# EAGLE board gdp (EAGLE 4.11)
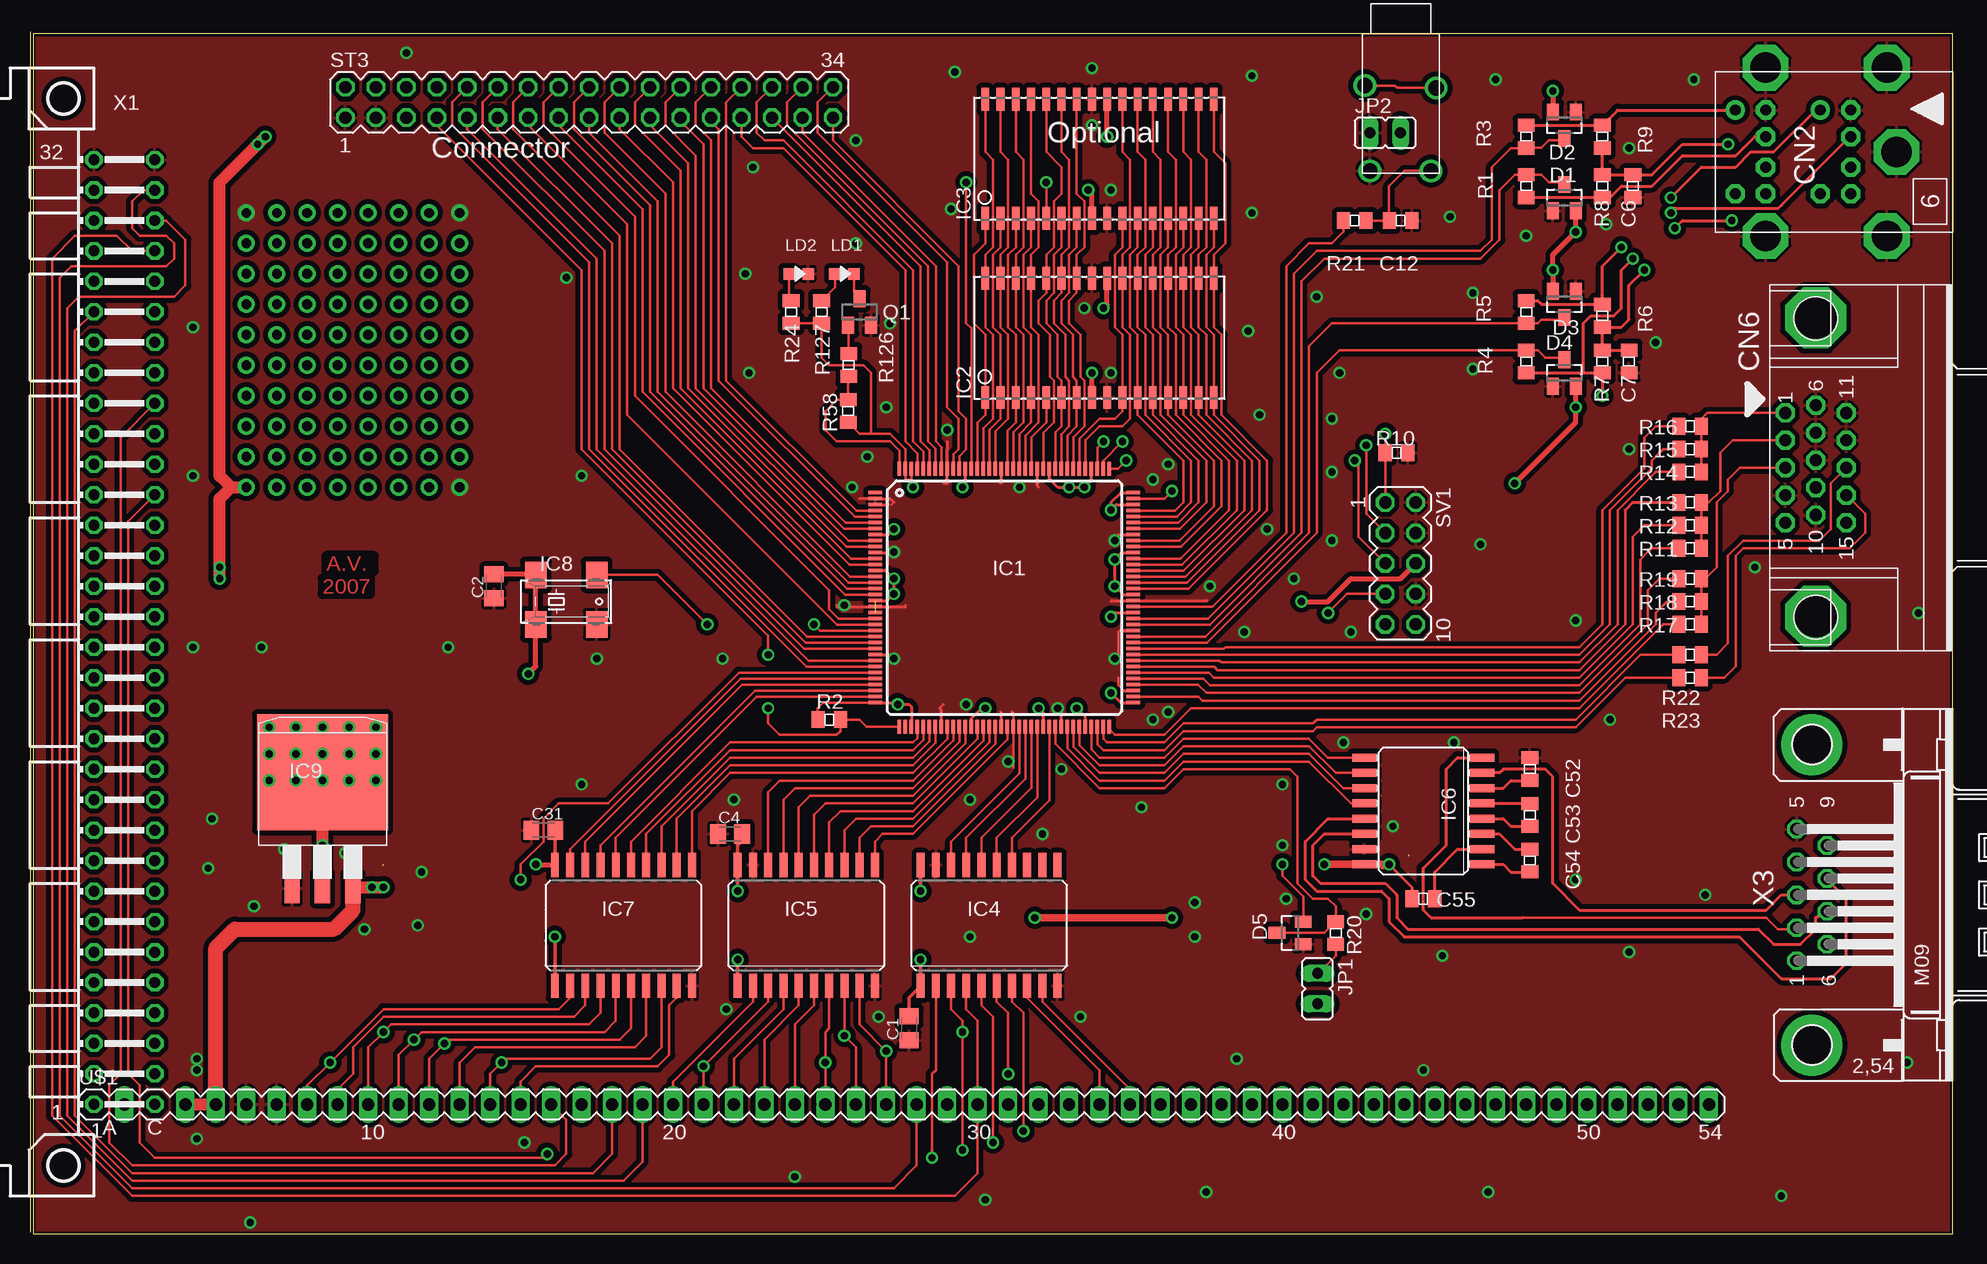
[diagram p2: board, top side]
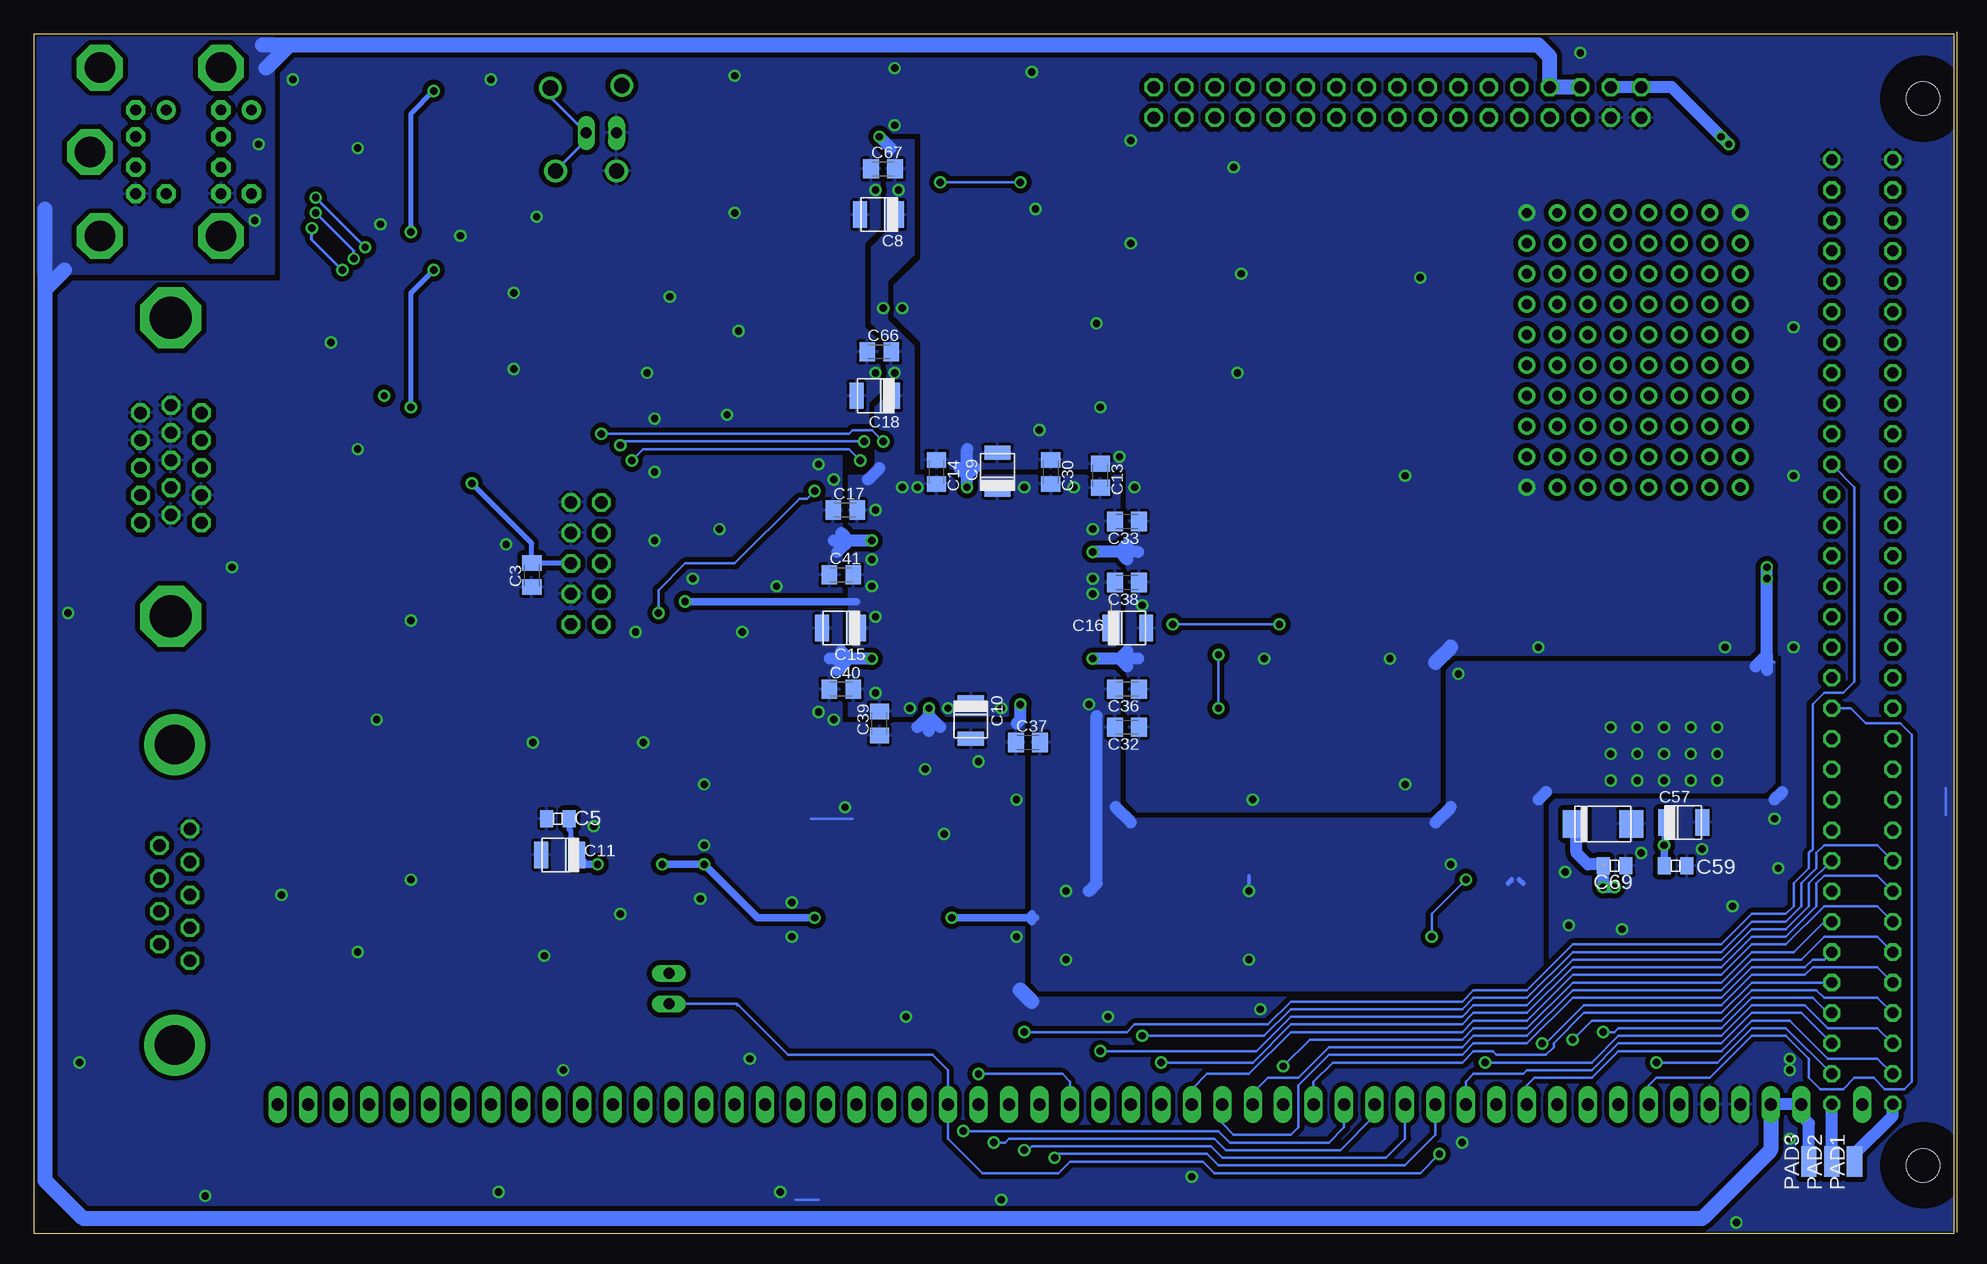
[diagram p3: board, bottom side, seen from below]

Size 160.25 x 100.18 mm. Coordinates in mm from the lower left corner, seen from the top.
Outline: 0.25,0 160.25,0 160.25,100 0.25,100 0.25,0
Copper layers (1*16): Top 0.035mm / dielectric 1.5mm / Bottom 0.035mm
Design rules "default": minimum track width 8mil, minimum drill 24mil, track to track 8mil, track to pad 8mil, pad to pad 8mil, via to via 8mil, smd to smd 8mil, copper to edge 0mil, drill to drill 8mil, minimum pad ring 10mil, minimum via ring 8mil, stop-mask expansion 4mil, vias tented up to drill 30mil, thermal gap 10mil

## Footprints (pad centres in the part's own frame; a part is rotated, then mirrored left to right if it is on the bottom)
C0805K = smd 1.3 x 1.6: 1 -1,0; 2 1,0
0805 = smd 1.092 x 1.397: 1 -0.94,0; 2 0.94,0
TANT_B = smd 1.15 x 2.2: 1 -1.473,0; 2 1.6,0
TANT_C = smd 2 x 2.3: 1 -2.032,0; 2 2.667,0
KLINKE3,5 = drill 1.27 round: 1 4.31,0.2; 2 11.43,0.635; 3 11.43,5.715; 4 4.51,6.15
MINIDIN_6POL_DOUBLE = drill 0.914 pad 1.6 octagon: A1 1.27,-8.5; A2 -1.27,-8.5; A3 3.493,-8.5; A4 -3.493,-8.5; A5 3.493,-11.04; B1 1.27,-15.6; B2 -1.27,-15.6; B3 3.493,-15.6; B4 -3.493,-15.6; B5 3.493,-18.14 | drill 0.914 pad 1.6 round: A6 -3.493,-11.04; B6 -3.493,-18.14 | drill 2.54 pad 3.81 octagon: SH1 0,-4.69; SH2 -7.018,-5.5; SH3 7.018,-5.5; SH4 -7.018,-15.6; SH5 7.018,-15.6
D-HD15F2 = drill 1.016 pad 1.575 octagon: 1 -4.826,-2.54; 2 -2.54,-2.54; 3 -0.254,-2.54; 4 2.032,-2.54; 5 4.318,-2.54; 6 -5.461,0; 7 -3.175,0; 8 -0.889,0; 9 1.397,0; 10 3.683,0; 11 -4.826,2.54; 12 -2.54,2.54; 13 -0.254,2.54; 14 2.032,2.54; 15 4.318,2.54 | drill 3.5 pad 5.08 octagon: PAD1 -12.754,0; PAD2 12.138,0
SOT23 = smd 1 x 1.4: 1 -0.95,-1.1; 2 0.95,-1.1; 3 0,1.1
TQFP144 = smd 1.143 x 0.297: 1 -10.75,8.75; 2 -10.75,8.25; 3 -10.75,7.75; 4 -10.75,7.25; 5 -10.75,6.75; 6 -10.75,6.25; 7 -10.75,5.75; 8 -10.75,5.25; 9 -10.75,4.75; 10 -10.75,4.25; 11 -10.75,3.75; 12 -10.75,3.25; 13 -10.75,2.75; 14 -10.75,2.25; 15 -10.75,1.75; 16 -10.75,1.25; 17 -10.75,0.75; 18 -10.75,0.25; 19 -10.75,-0.25; 20 -10.75,-0.75; 21 -10.75,-1.25; 22 -10.75,-1.75; 23 -10.75,-2.25; 24 -10.75,-2.75; 25 -10.75,-3.25; 26 -10.75,-3.75; 27 -10.75,-4.25; 28 -10.75,-4.75; 29 -10.75,-5.25; 30 -10.75,-5.75; 31 -10.75,-6.25; 32 -10.75,-6.75; 33 -10.75,-7.25; 34 -10.75,-7.75; 35 -10.75,-8.25; 36 -10.75,-8.75; 73 10.75,-8.75; 74 10.75,-8.25; 75 10.75,-7.75; 76 10.75,-7.25; 77 10.75,-6.75; 78 10.75,-6.25; 79 10.75,-5.75; 80 10.75,-5.25; 81 10.75,-4.75; 82 10.75,-4.25; 83 10.75,-3.75; 84 10.75,-3.25; 85 10.75,-2.75; 86 10.75,-2.25; 87 10.75,-1.75; 88 10.75,-1.25; 89 10.75,-0.75; 90 10.75,-0.25; 91 10.75,0.25; 92 10.75,0.75; 93 10.75,1.25; 94 10.75,1.75; 95 10.75,2.25; 96 10.75,2.75; 97 10.75,3.25; 98 10.75,3.75; 99 10.75,4.25; 100 10.75,4.75; 101 10.75,5.25; 102 10.75,5.75; 103 10.75,6.25; 104 10.75,6.75; 105 10.75,7.25; 106 10.75,7.75; 107 10.75,8.25; 108 10.75,8.75 | smd 0.297 x 1.143: 37 -8.75,-10.75; 38 -8.25,-10.75; 39 -7.75,-10.75; 40 -7.25,-10.75; 41 -6.75,-10.75; 42 -6.25,-10.75; 43 -5.75,-10.75; 44 -5.25,-10.75; 45 -4.75,-10.75; 46 -4.25,-10.75; 47 -3.75,-10.75; 48 -3.25,-10.75; 49 -2.75,-10.75; 50 -2.25,-10.75; 51 -1.75,-10.75; 52 -1.25,-10.75; 53 -0.75,-10.75; 54 -0.25,-10.75; 55 0.25,-10.75; 56 0.75,-10.75; 57 1.25,-10.75; 58 1.75,-10.75; 59 2.25,-10.75; 60 2.75,-10.75; 61 3.25,-10.75; 62 3.75,-10.75; 63 4.25,-10.75; 64 4.75,-10.75; 65 5.25,-10.75; 66 5.75,-10.75; 67 6.25,-10.75; 68 6.75,-10.75; 69 7.25,-10.75; 70 7.75,-10.75; 71 8.25,-10.75; 72 8.75,-10.75; 109 8.75,10.75; 110 8.25,10.75; 111 7.75,10.75; 112 7.25,10.75; 113 6.75,10.75; 114 6.25,10.75; 115 5.75,10.75; 116 5.25,10.75; 117 4.75,10.75; 118 4.25,10.75; 119 3.75,10.75; 120 3.25,10.75; 121 2.75,10.75; 122 2.25,10.75; 123 1.75,10.75; 124 1.25,10.75; 125 0.75,10.75; 126 0.25,10.75; 127 -0.25,10.75; 128 -0.75,10.75; 129 -1.25,10.75; 130 -1.75,10.75; 131 -2.25,10.75; 132 -2.75,10.75; 133 -3.25,10.75; 134 -3.75,10.75; 135 -4.25,10.75; 136 -4.75,10.75; 137 -5.25,10.75; 138 -5.75,10.75; 139 -6.25,10.75; 140 -6.75,10.75; 141 -7.25,10.75; 142 -7.75,10.75; 143 -8.25,10.75; 144 -8.75,10.75
SOJ32/4 = smd 0.635 x 1.905: 1 -8.89,-4.902; 2 -7.62,-4.902; 3 -6.35,-4.902; 4 -5.08,-4.902; 5 -3.81,-4.902; 6 -2.54,-4.902; 7 -1.27,-4.902; 8 0,-4.902; 9 1.27,-4.902; 10 2.54,-4.902; 11 3.81,-4.902; 12 5.08,-4.902; 13 6.35,-4.902; 14 7.62,-4.902; 15 8.89,-4.902; 16 10.16,-4.902; 17 10.16,5.029; 18 8.89,5.029; 19 7.62,5.029; 20 6.35,5.029; 21 5.08,5.029; 22 3.81,5.029; 23 2.54,5.029; 24 1.27,5.029; 25 0,5.029; 26 -1.27,5.029; 27 -2.54,5.029; 28 -3.81,5.029; 29 -5.08,5.029; 30 -6.35,5.029; 31 -7.62,5.029; 32 -8.89,5.029
SO20W = smd 0.66 x 2.032: 1 -5.715,-5.029; 2 -4.445,-5.029; 3 -3.175,-5.029; 4 -1.905,-5.029; 5 -0.635,-5.029; 6 0.635,-5.029; 7 1.905,-5.029; 8 3.175,-5.029; 9 4.445,-5.029; 10 5.715,-5.029; 11 5.715,5.029; 12 4.445,5.029; 13 3.175,5.029; 14 1.905,5.029; 15 0.635,5.029; 16 -0.635,5.029; 17 -1.905,5.029; 18 -3.175,5.029; 19 -4.445,5.029; 20 -5.715,5.029
SO16L = smd 0.66 x 2.032: 1 -4.445,-4.902; 2 -3.175,-4.902; 3 -1.905,-4.902; 4 -0.635,-4.902; 5 0.635,-4.902; 6 1.905,-4.902; 7 3.175,-4.902; 8 4.445,-4.902; 9 4.445,4.902; 10 3.175,4.902; 11 1.905,4.902; 12 0.635,4.902; 13 -0.635,4.902; 14 -1.905,4.902; 15 -3.175,4.902; 16 -4.445,4.902
CRYSTAL = smd 1.8 x 2.2: 1 -2.54,-2.857; 2 2.54,-2.857; 3 2.54,1.27; 4 -2.54,1.27
3LEAD_DD = smd 1.27 x 2.54: 1 -2.54,-3.556; 2 0,-3.556; 3 2.54,-3.556 | smd 10.922 x 9.652: 2@1 0,6.096
JP1 = drill 0.914 long: 1 0,-1.27; 2 0,1.27
0603LED = smd 0.965 x 0.965: 1 -0.787,0; 2 0.787,0
SMD2 = smd 1.27 x 2.54: 1 0,0
MA17-2 = drill 1.016 octagon: 1 -20.32,-1.27; 2 -20.32,1.27; 3 -17.78,-1.27; 4 -17.78,1.27; 5 -15.24,-1.27; 6 -15.24,1.27; 7 -12.7,-1.27; 8 -12.7,1.27; 9 -10.16,-1.27; 10 -10.16,1.27; 11 -7.62,-1.27; 12 -7.62,1.27; 13 -5.08,-1.27; 14 -5.08,1.27; 15 -2.54,-1.27; 16 -2.54,1.27; 17 0,-1.27; 18 0,1.27; 19 2.54,-1.27; 20 2.54,1.27; 21 5.08,-1.27; 22 5.08,1.27; 23 7.62,-1.27; 24 7.62,1.27; 25 10.16,-1.27; 26 10.16,1.27; 27 12.7,-1.27; 28 12.7,1.27; 29 15.24,-1.27; 30 15.24,1.27; 31 17.78,-1.27; 32 17.78,1.27; 33 20.32,-1.27; 34 20.32,1.27
MA05-2 = drill 1.016 octagon: 1 -5.08,-1.27; 2 -5.08,1.27; 3 -2.54,-1.27; 4 -2.54,1.27; 5 0,-1.27; 6 0,1.27; 7 2.54,-1.27; 8 2.54,1.27; 9 5.08,-1.27; 10 5.08,1.27
NKC-BUS = drill 1.016 long: 2 2.54,0; 4 7.62,0; 5 10.16,0; 6 12.7,0; 7 15.24,0; 8 17.78,0; 9 20.32,0; 10 22.86,0; 11 25.4,0; 12 27.94,0; 13 30.48,0; 14 33.02,0; 15 35.56,0; 16 38.1,0; 17 40.64,0; 18 43.18,0; 19 45.72,0; 20 48.26,0; 21 50.8,0; 22 53.34,0; 23 55.88,0; 24 58.42,0; 25 60.96,0; 26 63.5,0; 27 66.04,0; 28 68.58,0; 29 71.12,0; 30 73.66,0; 31 76.2,0; 32 78.74,0; 33 81.28,0; 34 83.82,0; 35 86.36,0; 36 88.9,0; 37 91.44,0; 38 93.98,0; 39 96.52,0; 40 99.06,0; 41 101.6,0; 42 104.14,0; 43 106.68,0; 44 109.22,0; 45 111.76,0; 46 114.3,0; 47 116.84,0; 48 119.38,0; 49 121.92,0; 50 124.46,0; 51 127,0; 52 129.54,0; 53 132.08,0; 54 134.62,0
ML64ECB = drill 0.914 octagon: 10C -7.62,16.51; 11C -7.62,13.97; 12A -2.54,11.43; 12C -7.62,11.43; 13A -2.54,8.89; 13C -7.62,8.89; 14A -2.54,6.35; 15A -2.54,3.81; 15C -7.62,3.81; 16A -2.54,1.27; 16C -7.62,1.27; 17A -2.54,-1.27; 19A -2.54,-6.35; 19C -7.62,-6.35; 21A -2.54,-11.43; 22A -2.54,-13.97; 23A -2.54,-16.51; 23C -7.62,-16.51; 24A -2.54,-19.05; 25A -2.54,-21.59; 26A -2.54,-24.13; 26C -7.62,-24.13; +5V -2.54,39.37; +5V@1 -7.62,39.37; A0 -7.62,29.21; A1 -7.62,24.13; A2 -2.54,26.67; A3 -7.62,26.67; A4 -2.54,24.13; A5 -2.54,21.59; A6 -2.54,19.05; A7 -7.62,19.05; A8 -7.62,21.59; A9 -2.54,-34.29; A10 -7.62,-3.81; A11 -7.62,-1.27; A12 -7.62,-26.67; A13 -2.54,-31.75; A14 -2.54,-3.81; A15 -7.62,-29.21; BUSAK -2.54,-36.83; BUSRQ -2.54,13.97; CLK -7.62,-31.75; D0 -7.62,36.83; D1 -7.62,6.35; D2 -7.62,31.75; D3 -2.54,31.75; D4 -2.54,29.21; D5 -2.54,36.83; D6 -2.54,34.29; D7 -7.62,34.29; GND -2.54,-39.37; GND@1 -7.62,-39.37; HALT -7.62,-21.59; INT -7.62,-11.43; IORQ -2.54,-26.67; M1 -2.54,-8.89; MREQ -7.62,-34.29; NMI -7.62,-8.89; RD -7.62,-19.05; RESET -7.62,-36.83; RFSH -2.54,-29.21; WAIT -2.54,16.51; WR -7.62,-13.97 | hole 2.794: 0,44.45; 0,-44.45
M09HP = drill 1.016 octagon: 1 5.486,-1.27; 2 2.743,-1.27; 3 0,-1.27; 4 -2.743,-1.27; 5 -5.486,-1.27; 6 4.115,1.27; 7 1.372,1.27; 8 -1.372,1.27; 9 -4.115,1.27 | drill 3.302 pad 5.08 round: G1 12.522,0; G2 -12.522,0

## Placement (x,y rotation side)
C1  100n  [C0805K]  73.28,17.14 90 top
C2  100n  [C0805K]  38.67,53.98 90 top
C3  100n  [C0805K]  118.76,54.9 90 bottom
C4  100n  [C0805K]  58.36,33.34 0 top
C5  100n  [0805]  116.58,34.61 0 bottom
C6  100n  [0805]  133.6,87.31 90 top
C7  100n  [0805]  133.29,72.71 90 top
C8  10µF  [TANT_B]  89.8,84.95 180 bottom
C9  10µF  [TANT_B]  79.95,63.5 90 bottom
C10  10µF  [TANT_B]  82.17,42.86 270 bottom
C11  10µF  [TANT_B]  116.38,31.59 180 bottom
C12  4n7  [0805]  114.24,84.45 180 top
C13  100n  [C0805K]  71.37,63.18 270 bottom
C14  100n  [C0805K]  85.03,63.5 270 bottom
C15  10µF  [TANT_B]  92.96,50.48 180 bottom
C16  10µF  [TANT_B]  69.15,50.48 0 bottom
C17  100n  [C0805K]  92.65,60.33 0 bottom
C18  10µF  [TANT_B]  90.11,69.85 180 bottom
C30  100n  [C0805K]  75.5,63.5 270 bottom
C31  100n  [C0805K]  42.8,33.66 0 top
C32  100n  [C0805K]  69.15,42.23 180 bottom
C33  100n  [C0805K]  69.15,59.37 180 bottom
C36  100n  [C0805K]  69.15,45.4 180 bottom
C37  100n  [C0805K]  77.41,40.96 0 bottom
C38  100n  [C0805K]  69.15,54.29 180 bottom
C39  100n  [C0805K]  89.79,42.55 90 bottom
C40  100n  [C0805K]  92.96,45.4 0 bottom
C41  100n  [C0805K]  92.96,54.93 0 bottom
C52  100n  [0805]  125.03,38.73 270 top
C53  100n  [0805]  125.03,34.92 270 top
C54  100n  [0805]  125.03,31.11 270 top
C55  100n  [0805]  116.14,27.94 180 top
C57  10µF  [TANT_B]  22.8,34.29 0 bottom
C59  100n  [0805]  23.43,30.68 180 bottom
C63  10µF/16V  [TANT_C]  29.78,34.18 0 bottom
C66  100n  [C0805K]  89.8,73.52 0 bottom
C67  100n  [C0805K]  89.48,88.76 0 bottom
C69  100n  [0805]  28.51,30.68 180 bottom
CN1  LINE OUT  [KLINKE3,5]  111.06,100.01 270 top
CN2  [MINIDIN_6POL_DOUBLE]  160.27,90.17 270 top
CN6  VGA15  [D-HD15F2]  148.84,63.59 270 top
D1  BAT54S  [SOT23]  127.89,86.36 0 top
D2  BAT54S  [SOT23]  127.89,92.39 180 top
D3  BAT54S  [SOT23]  127.89,77.47 180 top
D4  BAT54S  [SOT23]  127.89,71.75 0 top
D5  BAT54S  [SOT23]  105.03,25.08 90 top
IC1  LFXP6KC-T144  [TQFP144]  81.22,53.02 0 top
IC2  CY7C1019CV33-12VC  [SOJ32/4]  88.52,74.61 0 top
IC3  CY7C1019CV33-12VC  [SOJ32/4]  88.52,89.53 0 top
IC4  74LVC245  [SO20W]  79.95,25.72 0 top
IC5  74LVC245  [SO20W]  64.71,25.72 0 top
IC6  MAX3232CSE  [SO16L]  116.14,35.24 90 top
IC7  74LVC245  [SO20W]  49.47,25.72 0 top
IC8  40MHz  [CRYSTAL]  44.7,53.66 0 top
IC9  LT1086CM-3.3  [3LEAD_DD]  24.38,32.38 0 top
JP1  [JP1]  107.33,20.44 180 top
JP2  [JP1]  112.97,91.76 270 top
LD1  gelb  [0603LED]  67.88,80.01 0 top
LD2  Grün  [0603LED]  64.07,80.01 0 top
PAD1  [SMD2]  8.51,6.03 0 bottom
PAD2  [SMD2]  10.41,6.03 0 bottom
PAD3  [SMD2]  12.32,6.03 0 bottom
Q1  BSS138  [SOT23]  69.15,76.83 0 top
R1  120  [0805]  124.71,87.31 270 top
R2  4k7  [0805]  66.61,42.86 180 top
R3  120  [0805]  124.71,91.44 90 top
R4  120  [0805]  124.71,72.71 270 top
R5  120  [0805]  124.71,76.83 90 top
R6  2k  [0805]  131.06,76.52 270 top
R7  2k  [0805]  131.06,72.71 90 top
R8  2k  [0805]  131.06,87.31 90 top
R9  2k  [0805]  131.06,91.44 270 top
R10  4k7  [0805]  113.9,65.11 180 top
R11  470  [0805]  138.37,57.15 180 top
R12  1k  [0805]  138.37,59.05 180 top
R13  1k8  [0805]  138.37,60.96 180 top
R14  470  [0805]  138.37,63.5 180 top
R15  1k  [0805]  138.37,65.41 180 top
R16  1k8  [0805]  138.37,67.31 180 top
R17  470  [0805]  138.37,50.8 180 top
R18  1k  [0805]  138.37,52.7 180 top
R19  1k8  [0805]  138.37,54.61 180 top
R20  120R  [0805]  108.84,25.08 90 top
R21  3k3  [0805]  110.43,84.45 180 top
R22  47  [0805]  138.37,48.26 180 top
R23  47  [0805]  138.37,46.35 180 top
R24  270R  [0805]  63.44,76.83 270 top
R58  10k  [0805]  68.2,68.58 270 top
R126  5K6  [0805]  68.24,72.42 90 top
R127  220R  [0805]  65.98,76.83 270 top
ST3  [MA17-2]  46.61,94.3 0 top
SV1  [MA05-2]  114.24,55.88 270 top
U$1  NKC-BUS  [NKC-BUS]  5.33,10.79 0 top
X1  ECB64  [ML64ECB]  2.79,50.16 180 top
X3  DB9-M  [M09HP]  148.53,28.26 270 top

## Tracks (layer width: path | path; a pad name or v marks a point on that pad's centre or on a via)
/BUS_INT  (via drill 0.61)
  Top 0.203: X1.INT 8.19,59.37 8.19,13.34 9.14,12.38 9.14,7.62 10.41,6.35 42.8,6.35 v43.12,6.67
  Bottom 0.203: JP1.2 101.65,19.17 101.65,19.05 101.54,19.05 97.41,14.92 85.34,14.92 84.07,13.65 U$1.32 84.07,7.94 81.22,5.08 74.87,5.08 73.91,6.03 62.8,6.03 61.85,5.08 44.7,5.08 v43.12,6.67
A0
  Top 0.203: 60.26,20.32 60.26,20 | 60.26,20.32 IC5.2 | 60.26,20.32 60.26,19.37 53.59,12.7 U$1.20
  Bottom 0.203: X1.A0 17.08,20.95 19.62,18.41 31.05,18.41 33.59,15.88 33.59,15.56 34.23,14.92 38.35,14.92 38.67,15.24 40.26,15.24 41.21,14.29 52.01,14.29 53.59,12.7 U$1.20
A1  (via drill 0.61)
  Top 0.203: IC5.3 61.53,19.37 v56.13,13.97 U$1.21
  Bottom 0.203: X1.A1 11.05,26.04 13.59,23.5 17.08,23.5 19.62,20.95 32,20.95 35.81,17.14 40.26,17.14 41.21,16.19 53.91,16.19 v56.13,13.97
A2
  Top 0.203: IC5.4 62.8,18.73 58.67,14.61 U$1.22
  Bottom 0.203: X1.A2 6.6,24.77 11.05,24.77 12.95,22.86 17.08,22.86 19.62,20.32 32,20.32 35.81,16.51 40.26,16.51 41.21,15.56 52.32,15.56 54.86,13.02 57.4,13.02 58.67,11.75 U$1.22
A3
  Top 0.203: IC5.5 64.07,19.05 61.21,16.19 U$1.23
  Bottom 0.203: X1.A3 11.05,22.86 12,22.86 12.64,22.23 17.08,22.23 19.62,19.68 32,19.68 35.81,15.88 40.26,15.88 41.21,14.92 52.32,14.92 54.86,12.38 54.86,8.89 55.5,8.26 60.26,8.26 61.21,9.21 U$1.23
A4
  Top 0.203: IC5.6 65.34,19.05 63.75,17.46 U$1.24
  Bottom 0.203: X1.A4 6.6,27.3 11.05,27.3 14.22,24.13 17.08,24.13 19.62,21.59 32,21.59 35.81,17.78 40.26,17.78 41.21,16.83 55.5,16.83 58.99,13.34 62.48,13.34 63.75,12.06 U$1.24
A5  (via drill 0.61)
  Top 0.203: U$1.25 v66.29,14.29 66.29,16.83 66.61,17.14 IC5.7
  Bottom 0.203: X1.A5 6.6,29.84 11.05,29.84 11.68,29.21 11.68,27.3 14.22,24.77 17.08,24.77 19.62,22.23 32,22.23 35.81,18.41 40.26,18.41 41.21,17.46 55.5,17.46 58.67,14.29 v66.29,14.29
A6  (via drill 0.61)
  Top 0.203: U$1.26 68.83,15.56 v67.88,16.51 IC5.8
  Bottom 0.203: X1.A6 6.6,32.38 11.05,32.38 11.68,31.75 11.68,30.48 12.95,29.21 12.95,27.3 14.22,26.04 17.08,26.04 19.62,23.5 32,23.5 35.81,19.68 40.26,19.68 41.21,18.73 55.5,18.73 57.72,16.51 v67.88,16.51
A7  (via drill 0.61)
  Top 0.203: U$1.27 v71.37,15.24 69.15,17.46 IC5.9
  Bottom 0.203: v71.37,15.24 58.36,15.24 55.5,18.1 41.21,18.1 40.26,19.05 35.81,19.05 32,22.86 19.62,22.86 17.08,25.4 14.22,25.4 12.32,27.3 12.32,29.21 X1.A7
A8
  Top 0.203: IC4.8 83.12,19.68 89.15,13.65 U$1.34
A9
  Top 0.203: U$1.35 91.69,12.06 84.39,19.37 IC4.9
AUDIO
  Top 0.203: IC1.89 98.56,52.27 104.71,58.42 104.71,80.64 106.62,82.55 108.52,82.55 109.49,83.52 R21.2
BLAU
  Top 0.203: R17.1 139.32,50.8 139.31,50.81 R18.1 139.32,52.7 139.31,52.72 R19.1 139.64,54.61 140.59,55.56 140.59,60.96 141.54,61.91 141.54,62.87 142.53,63.85 CN6.3
CLK
  Top 0.203: X1.CLK 8.51,81.92 7.24,83.19 3.75,83.19 1.84,81.28 1.84,9.84 8.51,3.17 77.09,3.17 78.99,5.08 U$1.30 78.99,17.78 78.04,18.73 IC4.4
CTS_FPGA
  Top 0.203: IC6.12 110.11,35.88 106.62,39.37 96.14,39.37 94.55,37.78 89.15,37.78 86.47,40.47 IC1.65
D0  (via drill 0.61)
  Top 0.203: IC7.2 45.02,19.68 44.07,18.73 29.46,18.73 v25.02,14.29 23.11,12.38 23.11,11.11 | 23.11,11.11 U$1.8 | 23.11,11.11 23.11,11.43
  Bottom 0.203: X1.D0 14.22,17.14 17.08,17.14 19.94,14.29 v25.02,14.29
D1
  Top 0.203: IC7.3 46.29,19.05 45.34,18.1 29.46,18.1 26.92,15.56 26.92,13.34 25.65,12.06 U$1.9
  Bottom 0.203: 9.78,43.81 X1.D1 8.83,43.81 7.56,42.55 4.7,42.55 3.75,41.59 3.75,12.7 4.38,12.06 5.97,12.06 6.92,13.02 8.51,13.02 9.46,12.06 11.37,12.06 12.32,13.02 12.32,14.61 14.22,16.51 17.08,16.51 20.57,13.02 25.02,13.02 25.65,12.38 U$1.9
D2  (via drill 0.61)
  Top 0.203: U$1.10 28.19,15.56 v29.46,16.83 30.1,17.46 46.61,17.46 47.56,18.41 IC7.4
  Bottom 0.203: X1.D2 10.73,18.41 12,19.68 17.08,19.68 19.62,17.14 28.19,17.14 28.51,16.83 v29.46,16.83
D3  (via drill 0.61)
  Top 0.203: IC7.5 48.83,17.78 47.88,16.83 32.64,16.83 v32,16.19 30.73,14.92 U$1.11
  Bottom 0.203: X1.D3 6.6,19.68 11.05,19.68 11.68,20.32 17.08,20.32 19.62,17.78 30.42,17.78 v32,16.19
D4  (via drill 0.61)
  Top 0.203: U$1.12 33.27,14.61 v34.54,15.88 34.86,16.19 49.15,16.19 50.1,17.14 IC7.6
  Bottom 0.203: X1.D4 6.6,22.23 12,22.23 12.64,21.59 17.08,21.59 19.62,19.05 31.05,19.05 34.23,15.88 v34.54,15.88
D5
  Top 0.203: IC7.7 51.37,16.51 50.42,15.56 37.08,15.56 35.81,14.29 U$1.13
  Bottom 0.203: X1.D5 6.6,14.61 10.73,14.61 13.91,17.78 17.08,17.78 19.62,15.24 28.19,15.24 30.42,13.02 35.18,13.02 35.81,12.38 U$1.13
D6  (via drill 0.61)
  Top 0.203: U$1.14 38.35,13.34 v39.31,14.29 39.62,14.61 51.69,14.61 52.64,15.56 IC7.8
  Bottom 0.203: X1.D6 6.6,17.14 10.73,17.14 12.64,19.05 17.08,19.05 19.62,16.51 28.19,16.51 30.42,14.29 v39.31,14.29
D7
  Top 0.203: U$1.15 40.89,12.7 42.16,13.97 52.32,13.97 53.28,14.92 53.28,19.05 53.91,19.68 IC7.9
  Bottom 0.203: X1.D7 12.95,18.41 17.08,18.41 19.62,15.88 28.19,15.88 30.42,13.65 35.81,13.65 36.13,13.34 40.26,13.34 40.89,12.7 U$1.15
DONE
  Top 0.203: R126.1 68.2,71.47 68.2,69.53 | IC1.144 72.47,65.27 71.69,66.04 67.25,66.04 66.29,66.99 66.29,68.58 67.25,69.53 68.2,69.53 | 68.2,69.53 R58.1
EXT0
  Top 0.203: ST3.10 35.18,94.3 35.18,92.39 46.61,80.96 46.61,65.41 64.74,47.27 IC1.30
EXT1
  Top 0.203: IC1.29 64.88,47.77 47.24,65.41 47.24,81.28 36.45,92.08 ST3.9
EXT2
  Top 0.203: ST3.12 37.72,94.3 37.72,92.08 47.88,81.92 47.88,65.41 64.51,48.77 IC1.27
EXT3
  Top 0.203: IC1.26 64.65,49.27 48.51,65.41 48.51,82.55 38.99,92.08 ST3.11
EXT4
  Top 0.203: ST3.14 40.26,94.3 40.26,92.08 49.15,83.19 49.15,65.41 64.78,49.77 IC1.25
EXT5
  Top 0.203: IC1.23 67.27,50.77 49.78,68.26 49.78,84.14 41.53,92.39 ST3.13
EXT6
  Top 0.203: ST3.16 42.8,94.3 42.8,92.39 50.42,84.77 50.42,69.85 66.61,53.66 66.61,52.07 67.41,51.27 IC1.22
EXT7
  Top 0.203: IC1.18 67.95,53.27 51.05,70.17 51.05,85.41 44.07,92.39 ST3.15
EXT8
  Top 0.203: IC1.17 68.08,53.77 51.69,70.17 51.69,85.72 45.34,92.08 45.34,94.3 ST3.18
EXT9
  Top 0.203: IC1.16 68.22,54.27 52.32,70.17 52.32,86.04 46.61,91.76 ST3.17
EXT10
  Top 0.203: IC1.15 68.35,54.77 52.96,70.17 52.96,86.68 47.88,91.76 47.88,94.3 ST3.20
EXT11
  Top 0.203: IC1.13 68.31,55.77 53.59,70.48 53.59,87.63 49.15,92.08 ST3.19
EXT12
  Top 0.203: ST3.22 50.42,94.3 50.42,92.39 54.23,88.58 54.23,70.48 68.44,56.27 IC1.12
EXT13
  Top 0.203: IC1.10 68.08,57.27 54.86,70.48 54.86,89.22 51.69,92.39 ST3.21
EXT14
  Top 0.203: ST3.24 52.96,94.3 52.96,92.39 55.5,89.85 55.5,70.48 68.21,57.77 IC1.9
EXT15
  Top 0.203: IC1.7 67.85,58.77 56.13,70.48 56.13,90.81 54.23,92.71 ST3.23
EXT16
  Top 0.203: IC1.6 67.98,59.27 56.77,70.48 56.77,91.12 55.5,92.39 55.5,94.3 ST3.26
EXT17
  Top 0.203: IC1.5 68.75,59.77 57.4,71.12 57.4,92.08 56.77,92.71 ST3.25
EXT18
  Top 0.203: IC1.4 68.89,60.27 58.04,71.12 58.04,94.3 ST3.28
EXT19
  Top 0.203: ST3.27 59.31,91.44 60.26,90.49 62.8,90.49 72.96,80.33 72.96,66.04 73.97,65.03 IC1.141
EXT20
  Top 0.203: ST3.30 60.58,94.3 60.58,91.76 61.21,91.12 62.8,91.12 73.6,80.33 73.6,66.04 74.47,65.17 IC1.140
EXT21
  Top 0.203: ST3.29 74.23,80.64 74.23,66.04 74.97,65.31 IC1.139
EXT22
  Top 0.203: ST3.32 63.12,94.3 63.12,92.39 74.87,80.64 74.87,66.04 75.47,65.44 IC1.138
EXT23
  Top 0.203: ST3.31 64.39,91.76 75.5,80.64 75.5,66.04 75.97,65.58 IC1.137
EXT24
  Top 0.203: ST3.34 65.66,94.3 65.66,91.76 76.45,80.96 76.45,68.9 77.41,67.94 77.41,65.41 76.97,64.97 IC1.135
EXT25
  Top 0.203: ST3.33 66.93,91.12 77.41,80.64 77.41,68.58 78.04,67.94 78.04,65.41 77.47,64.83 IC1.134
F_TCK  (via drill 0.61)
  Top 0.203: IC1.111 88.97,65.53 v89.47,66.04 | v112.97,66.67 112.97,65.09 | R10.2 SV1.1
  Top 0.254: 112.97,65.09 112.96,65.09 R10.2 | SV1.1
  Bottom 0.203: v112.97,66.67 92.33,66.67 92.01,66.99 90.42,66.99 v89.47,66.04
F_TDI  (via drill 0.61)
  Top 0.203: IC1.109 90.7,63.77 v91.38,64.45 | SV1.5 110.74,58.1 110.74,64.14 v110.43,64.45
  Bottom 0.203: v91.38,64.45 92.33,65.41 109.47,65.41 v110.43,64.45
F_TDO  (via drill 0.61)
  Top 0.203: SV1.7 109.79,53.34 v108.2,51.75 | IC1.107 94.55,61.27 v95.19,61.91
  Bottom 0.203: v108.2,51.75 108.2,53.66 105.98,55.88 101.85,55.88 96.46,61.28 95.82,61.28 v95.19,61.91
F_TMS  (via drill 0.61)
  Top 0.203: SV1.3 111.38,60.01 v111.38,65.72 | v91.06,66.04 89.47,64.45 89.47,63.82 IC1.110
  Bottom 0.203: v91.06,66.04 111.06,66.04 v111.38,65.72
GND  (via drill 0.61, 0.81 pad 1.42)
  Top 0.203: 90.74,58.1 90.74,58.27 | 83.97,62.34 84.07,62.23 | 80.9,62.55 80.97,62.62 | 76.14,62.55 76.3,62.71 76.47,62.88 | 71.69,61.28 71.69,61.27 71.7,61.27 72.01,60.96 71.82,60.77 | 69.16,61.27 69.15,61.28 | 75.97,43.67 75.82,43.81 | 80.97,43.43 80.9,43.5 | 91.19,45.27 90.74,45.72 90.74,46.35 | 90.74,48.26 90.74,50.16 90.85,50.27 90.95,50.27 91.06,50.27 | 72.01,48.27 72.01,48.26 | 67.25,52.27 67.25,52.39 | 72.96,52.27 72.96,52.39 | 81.97,38.85 IC1.56 81.97,43.38 81.85,43.5
  Top 0.254: 76.14,44.13 75.97,43.96 | IC1.11 71.63,56.77 71.69,56.83 | 90.74,58.27 IC1.101 | 83.97,62.34 IC1.121 | 80.97,62.62 IC1.127 | 71.69,61.27 IC1.2 69.16,61.27 | IC1.44 75.97,43.67 | IC1.54 80.97,43.43 | 91.19,45.27 IC1.75 | IC1.28 72.01,48.27 | 67.25,52.27 IC1.20 72.96,52.27 | 91.17,50.27 IC1.85 90.95,50.27 | IC1.64 85.97,43.48 | 98.11,52.77 IC1.90 90.17,52.77 90.11,52.7 | IC1.3 71.56,60.77 | IC2.9 89.8,69.71 | IC1.136 76.47,66.03 | 76.3,62.71 76.3,62.55 76.45,62.55 76.45,65.41
  Top 0.305: 85.97,43.48 85.98,43.5
  Top 0.406: D3.1 128.84,78.74
  Bottom 0.203: 92.01,34.61 95.5,34.61 | 0.89,34.92 0.89,37.15 | 94.87,2.86 96.77,2.86
  Bottom 1.016: v78.04,44.13 78.04,42.86 78.36,42.55 | 68.2,47.94 69.79,47.94 | 68.2,56.83 69.79,56.83 | 69.79,56.83 v72.01,56.83 | v82.49,62.23 82.49,65.41 | v90.42,57.78 92.33,57.78 | 92.33,57.78 93.6,57.78 | v90.42,47.94 92.33,47.94 | 92.33,47.94 93.92,47.94 | 85.66,43.18 85.66,41.91 | 85.66,43.18 v85.66,43.81 | 84.71,42.23 85.66,43.18 | 85.66,43.18 86.61,42.23 | 92.33,47.94 93.28,46.99 | 92.33,47.94 92.96,48.58 | 92.33,57.78 93.28,56.83 | 92.33,57.78 92.96,58.42 | 81.85,63.82 82.49,63.18 83.12,63.82 | 69.79,56.83 69.15,57.47 | 69.79,56.83 69.15,56.2 | 69.79,47.94 69.15,48.58 | 69.79,47.94 69.15,47.31 | 14.54,36.83 15.18,36.2 | 69.79,47.94 v72.01,47.94
  Bottom 1.27: 43.43,47.62 42.16,48.9 | 77.09,19.37 78.04,20.32
  other vias: 45.97,63.18 93.6,42.86 59.94,71.75 116.14,13.65 92.65,35.56 100.58,14.61 44.7,79.69 94.87,64.14 90.11,87 88.52,92.39 120.27,72.07 90.11,71.75 87.88,77.15 124.71,83.19 108.52,63.5 108.52,57.78 101.54,75.25 101.85,85.09 120.27,78.42 118.36,84.77 122.17,96.2 97.09,27.62 97.09,24.77 111.38,26.67 98.04,3.49 121.54,3.49 117.73,23.18 78.36,24.77 133.29,23.5 139.64,28.26 145.99,3.17 131.7,42.86 104.39,37.47 113.6,33.97 128.84,29.53 101.22,50.16 76.77,85.41 77.09,96.84 133.29,90.49 105.35,54.61 110.11,50.16 102.49,68.26 109.16,71.75 109.47,40.96 98.36,53.98 103.12,58.74 135.51,74.3 104.39,32.38 104.71,27.94 157.42,51.75 88.52,97.16 18.67,27.3 32.32,25.72 14.86,30.48 15.18,34.61 13.91,13.65 13.91,14.61 26.29,31.75 32.64,30.16 13.91,7.94 18.35,0.95 58.67,36.2 78.36,36.2 87.57,18.1 70.74,18.1 131.38,84.14 67.88,52.39 68.52,62.23 71.37,68.9 60.26,88.9 68.83,82.55 19.3,48.9 34.86,48.9 47.24,47.94 57.72,47.94 13.59,48.9 13.59,63.18 13.59,75.56 31.37,98.42 84.39,33.34 27.88,25.4 45.97,37.47 107.25,78.11 156.46,14.29 101.85,96.52 118.68,40.96 128.84,51.12 133.29,65.41 18.03,85.09 35.81,62.23 35.81,85.09 59.63,80.01 143.76,55.56 108.52,67.94 21.21,32.07 41.21,7.62 63.75,4.76 79.63,2.86 58.04,18.73 85.98,38.73 81.53,39.37 120.9,57.47 68.83,91.12 71.69,75.88 76.45,66.99 93.6,62.87 138.68,96.2 69.79,64.77 94.87,43.5
  pour Top (isolate 0.406): 0.57,0.32 159.96,0.32 159.96,99.69 0.57,99.69
  pour Bottom (isolate 0.406): 0.25,48.26 69.15,48.26 69.15,99.69 0.25,99.69
  pour Bottom (isolate 0.406): 67.88,63.82 86.3,63.82 86.3,100.01 67.88,99.69
  pour Bottom (isolate 0.406): 92.96,99.69 139.64,99.69 139.64,32.7 92.96,32.7
  pour Bottom (isolate 0.406): 107.25,79.35 159.96,79.38 159.96,0.32 107.25,0.32
  pour Bottom (isolate 0.406): 93.6,0.32 113.6,0.32 113.6,35.88 93.6,35.88
  pour Bottom (isolate 0.406): 93.92,42.55 93.92,18.73 77.72,18.73 77.72,42.55
  pour Bottom (isolate 0.406): 86.3,74.3 88.52,76.52 88.52,79.06 86.3,81.28
  pour Bottom (isolate 0.406): 85.98,99.69 93.6,99.69 93.6,91.76 85.98,91.76
  pour Bottom (isolate 0.406): 93.92,93.98 89.79,93.98 89.79,83.82 91.06,82.55 91.06,75.56 89.79,74.3 89.79,70.17 90.74,69.22 90.74,65.09 93.92,65.09
  pour Bottom (isolate 0.406): 33.91,0.32 33.91,36.2 0.25,36.2 0.25,0.32
  pour Bottom (isolate 0.406): 0.25,48.58 14.54,48.58 14.54,35.56 0.25,35.56
  pour Bottom (isolate 0.406): 43.12,35.24 43.12,48.58 69.15,48.58 69.15,35.24
  pour Bottom (isolate 0.406): 32.32,0.32 32.32,19.68 96.77,19.68 96.77,0.32
GRUEN
  Top 0.203: R11.1 139.32,57.15 139.31,57.16 R12.1 139.32,59.05 139.31,59.07 R13.1 139.95,60.96 140.91,61.91 140.91,65.09 141.95,66.14 CN6.2
INT
  Top 0.203: IC1.63 85.47,40.84 89.15,37.15 94.55,37.15 96.14,38.73 105.03,38.73 105.66,38.1 105.66,29.21 106.93,27.94 108.2,27.94 108.84,27.3 108.84,26.04 | 108.84,26.04 108.84,26.35 | D5.3 107.89,25.08 108.84,26.04 | 108.84,26.04 R20.2
IORQ  (via drill 0.61)
  Top 0.203: U$1.18 48.51,6.67 46.93,5.08 8.51,5.08 3.75,9.84 3.75,75.25 X1.IORQ | v80.26,7.62 80.26,18.1 79.31,19.05 IC4.5
  Bottom 0.203: U$1.18 48.51,9.84 51.37,6.99 60.9,6.99 61.85,7.94 78.99,7.94 79.31,7.62 v80.26,7.62
MREQ  (via drill 0.61)
  Top 0.203: U$1.19 51.05,6.03 49.47,4.45 8.51,4.45 3.11,9.84 3.11,77.15 4.06,78.11 12,78.11 12.95,79.06 12.95,82.87 11.37,84.45 X1.MREQ | v82.8,8.57 82.8,18.41 81.85,19.37 IC4.7
  Bottom 0.203: U$1.19 51.05,8.89 52.32,7.62 60.58,7.62 61.53,8.57 v82.8,8.57
N$1  (via drill 0.61)
  Top 0.203: IC1.24 65.87,50.27 v65.34,50.8 | IC8.3 52.32,54.93 v56.45,50.8
  Bottom 0.203: v56.45,50.8 v65.34,50.8
N$2
  Bottom 0.61: PAD1.1 8.51,6.67
  Bottom 1.016: X1.+5V 5.33,9.84 8.51,6.67
N$3
  Top 0.203: 63.12,80.01 LD2.1 63.28,77.94 63.44,77.79 R24.1
N$4
  Top 0.254: IC6.14 107.89,33.34 106.93,32.38 106.93,29.84 107.57,29.21 112.97,29.21 113.92,28.26 113.92,26.35 114.87,25.4 144.08,25.4 145.35,24.13 147.57,24.13 148.84,25.4 148.84,26.35 149.8,26.99 X3.7
N$5
  Top 0.254: IC6.13 108.2,34.61 106.3,32.7 106.3,29.53 107.25,28.57 112.65,28.57 113.28,27.94 113.28,26.04 114.55,24.77 142.49,24.77 145.99,21.27 150.11,21.27 151.38,22.54 151.38,27.94 149.8,29.53 X3.8
N$7  (via drill 0.61)
  Top 0.254: R4.2 124.71,71.75 129.48,71.75 | 129.48,71.75 131.06,71.75 | R7.1 v131.06,69.85 | v133.6,81.28 132.65,80.33 132.65,77.15 132.02,76.52 130.11,76.52 129.48,75.88 129.48,71.75 | v136.78,85.09 137.1,85.48 145.75,85.48 145.99,85.72 151.7,91.44 CN2.A2
  Top 0.406: 131.06,71.75 R7.1
  Bottom 0.254: v136.78,85.09 133.6,81.92 v133.6,81.28
N$8
  Top 0.254: IC6.1 122.81,30.8 123.44,30.16 125.03,30.16 C54.2 125.03,30.24
N$9  (via drill 0.61)
  Top 0.254: R5.2 124.71,77.79 125.67,77.79 125.98,77.47 R6.1 | R6.1 131.06,80.64 v132.65,82.23 | v136.78,86.36 139.32,88.9 142.18,88.9 143.45,90.17 145.35,90.17 148.84,93.66 CN2.A6
  Top 0.406: R6.1
  Bottom 0.254: v132.65,82.23 v136.78,86.36
N$10
  Top 0.203: R8.1 131.71,86.37
  Top 0.254: R1.2 124.73,86.37 R8.1 | 131.71,86.37 132.65,87.31 135.19,87.31 137.73,89.85 142.18,89.85 142.81,90.49 143.76,91.44 CN2.B2
N$11
  Top 0.254: R3.2 124.71,92.39 131.06,92.39 132.33,93.66 CN2.B6
  Top 0.406: 131.06,92.39 R9.1
N$18
  Bottom 1.016: PAD2.1 X1.+5V@1
N$20
  Top 0.254: IC6.3 122.49,33.34 123.76,32.07 125.03,32.07 | 125.03,32.07 125.03,32.12 | 125.03,32.07 C54.1
N$22
  Top 0.254: IC6.4 122.81,34.61 123.44,33.97 125.03,33.97 C53.2 125.03,34.05
N$23
  Top 0.254: 125.35,35.88 125.35,35.93 | 125.35,35.88 C53.1 | IC6.5 125.35,35.88
N$27
  Top 0.203: R20.1 108.84,23.18 107.37,21.71 JP1.1
N$28
  Top 0.203: 113.6,84.45 C12.2 | R21.1 C12.2 | CN1.3 114.55,88.58 113.28,87.31 C12.2 | CN1.1 113.78,95.7 113.98,95.5 CN1.4
  Bottom 0.254: CN1.4 117.21,94.73 JP2.2 114.24,91.12 CN1.3
N$30
  Top 0.203: R22.1 140.59,48.26 141.54,49.21 141.54,56.52 142.81,57.78 149.16,57.78 150.11,58.74 150.11,62.55 151.38,63.82 CN6.13
N$36
  Top 0.203: R23.1 141.22,46.35 142.18,47.31 142.18,56.52 142.81,57.15 151.7,57.15 152.97,58.42 152.97,60.01 151.38,61.59 CN6.14
N$37  (via drill 0.81 pad 1.42)
  other vias: 20.57,85.09
N$38  (via drill 0.81 pad 1.42)
  other vias: 23.11,85.09
N$39  (via drill 0.81 pad 1.42)
  other vias: 25.65,85.09
N$40  (via drill 0.81 pad 1.42)
  other vias: 28.19,85.09
N$41  (via drill 0.81 pad 1.42)
  other vias: 30.73,85.09
N$42  (via drill 0.81 pad 1.42)
  other vias: 33.27,85.09
N$44  (via drill 0.81 pad 1.42)
  other vias: 35.81,82.55
N$46  (via drill 0.81 pad 1.42)
  other vias: 33.27,82.55
N$47  (via drill 0.81 pad 1.42)
  other vias: 30.73,82.55
N$48  (via drill 0.81 pad 1.42)
  other vias: 28.19,82.55
N$49  (via drill 0.81 pad 1.42)
  other vias: 25.65,82.55
N$50  (via drill 0.81 pad 1.42)
  other vias: 23.11,82.55
N$51  (via drill 0.81 pad 1.42)
  other vias: 20.57,82.55
N$52  (via drill 0.81 pad 1.42)
  other vias: 18.03,82.55
N$53  (via drill 0.81 pad 1.42)
  other vias: 18.03,80.01
N$54  (via drill 0.81 pad 1.42)
  other vias: 18.03,77.47
N$55  (via drill 0.81 pad 1.42)
  other vias: 18.03,74.93
N$56  (via drill 0.81 pad 1.42)
  other vias: 18.03,72.39
N$57  (via drill 0.81 pad 1.42)
  other vias: 18.03,69.85
N$58  (via drill 0.81 pad 1.42)
  other vias: 18.03,67.31
N$59  (via drill 0.81 pad 1.42)
  other vias: 18.03,64.77
N$61  (via drill 0.81 pad 1.42)
  other vias: 20.57,62.23
N$62  (via drill 0.81 pad 1.42)
  other vias: 23.11,62.23
N$63  (via drill 0.81 pad 1.42)
  other vias: 25.65,62.23
N$65  (via drill 0.81 pad 1.42)
  other vias: 28.19,62.23
N$66  (via drill 0.81 pad 1.42)
  other vias: 30.73,62.23
N$67  (via drill 0.81 pad 1.42)
  other vias: 33.27,62.23
N$69  (via drill 0.81 pad 1.42)
  other vias: 35.81,64.77
N$70  (via drill 0.81 pad 1.42)
  other vias: 35.81,67.31
N$71  (via drill 0.81 pad 1.42)
  other vias: 35.81,69.85
N$72  (via drill 0.81 pad 1.42)
  other vias: 35.81,72.39
N$73  (via drill 0.81 pad 1.42)
  other vias: 35.81,74.93
N$74  (via drill 0.81 pad 1.42)
  other vias: 35.81,77.47
N$75  (via drill 0.81 pad 1.42)
  other vias: 35.81,80.01
N$76  (via drill 0.81 pad 1.42)
  other vias: 20.57,64.77
N$77  (via drill 0.81 pad 1.42)
  other vias: 23.11,64.77
N$78  (via drill 0.81 pad 1.42)
  other vias: 25.65,64.77
N$79  (via drill 0.81 pad 1.42)
  other vias: 28.19,64.77
N$80
  Top 0.203: R127.1 65.98,77.79 67.09,78.91 LD1.1
N$81  (via drill 0.81 pad 1.42)
  other vias: 30.73,64.77
N$82  (via drill 0.81 pad 1.42)
  other vias: 20.57,80.01
N$83  (via drill 0.81 pad 1.42)
  other vias: 20.57,77.47
N$84  (via drill 0.81 pad 1.42)
  other vias: 20.57,74.93
N$85  (via drill 0.81 pad 1.42)
  other vias: 20.57,72.39
N$86  (via drill 0.81 pad 1.42)
  other vias: 20.57,69.85
N$87  (via drill 0.81 pad 1.42)
  other vias: 20.57,67.31
N$88  (via drill 0.81 pad 1.42)
  other vias: 23.11,67.31
N$89
  Top 0.203: Q1.3 69.15,78.11 68.67,78.59 LD1.2
N$90  (via drill 0.81 pad 1.42)
  other vias: 25.65,67.31
N$91  (via drill 0.81 pad 1.42)
  other vias: 28.19,67.31
N$92
  Top 0.203: Q1.1 68.2,75.88 68.24,75.84 R126.2
N$93  (via drill 0.81 pad 1.42)
  other vias: 30.73,67.31
N$94  (via drill 0.81 pad 1.42)
  other vias: 33.27,67.31
N$95  (via drill 0.81 pad 1.42)
  other vias: 33.27,69.85
N$96  (via drill 0.81 pad 1.42)
  other vias: 33.27,72.39
N$97  (via drill 0.81 pad 1.42)
  other vias: 33.27,74.93
N$98  (via drill 0.81 pad 1.42)
  other vias: 33.27,77.47
N$99  (via drill 0.81 pad 1.42)
  other vias: 33.27,80.01
N$100  (via drill 0.81 pad 1.42)
  other vias: 30.73,80.01
N$101  (via drill 0.81 pad 1.42)
  other vias: 28.19,80.01
N$103  (via drill 0.81 pad 1.42)
  other vias: 25.65,80.01
N$104  (via drill 0.81 pad 1.42)
  other vias: 23.11,80.01
N$105  (via drill 0.81 pad 1.42)
  other vias: 23.11,77.47
N$106  (via drill 0.81 pad 1.42)
  other vias: 23.11,74.93
N$107  (via drill 0.81 pad 1.42)
  other vias: 23.11,72.39
N$108  (via drill 0.81 pad 1.42)
  other vias: 23.11,69.85
N$109  (via drill 0.81 pad 1.42)
  other vias: 25.65,69.85
N$110  (via drill 0.81 pad 1.42)
  other vias: 28.19,69.85
N$111  (via drill 0.81 pad 1.42)
  other vias: 30.73,69.85
N$112  (via drill 0.81 pad 1.42)
  other vias: 33.27,64.77
N$113  (via drill 0.81 pad 1.42)
  other vias: 30.73,72.39
N$114  (via drill 0.81 pad 1.42)
  other vias: 30.73,74.93
N$115  (via drill 0.81 pad 1.42)
  other vias: 30.73,77.47
N$116  (via drill 0.81 pad 1.42)
  other vias: 28.19,77.47
N$117  (via drill 0.81 pad 1.42)
  other vias: 25.65,77.47
N$118  (via drill 0.81 pad 1.42)
  other vias: 25.65,74.93
N$119  (via drill 0.81 pad 1.42)
  other vias: 25.65,72.39
N$120  (via drill 0.81 pad 1.42)
  other vias: 28.19,72.39
N$121  (via drill 0.81 pad 1.42)
  other vias: 28.19,74.93
NA0
  Top 0.203: IC5.18 61.53,36.83 62.48,37.78 73.6,37.78 76.97,41.15 IC1.46
NA1
  Top 0.203: IC5.17 62.8,36.2 63.75,37.15 73.6,37.15 77.47,41.02 IC1.47
NA2
  Top 0.203: IC5.16 64.07,35.56 65.02,36.51 73.6,36.51 77.97,40.88 IC1.48
NA3
  Top 0.203: IC5.15 65.34,34.92 66.29,35.88 73.6,35.88 78.97,41.25 IC1.50
NA4
  Top 0.203: IC5.14 66.61,34.29 67.56,35.24 73.6,35.24 79.47,41.11 IC1.51
NA5
  Top 0.203: IC5.13 67.88,33.66 68.83,34.61 73.6,34.61 79.97,40.98 IC1.52
NA6
  Top 0.203: IC5.12 69.15,33.02 70.1,33.97 73.6,33.97 80.47,40.84 IC1.53
NA7
  Top 0.203: IC5.11 70.42,32.7 71.06,33.34 73.6,33.34 81.47,41.21 IC1.55
NCLK
  Top 0.203: IC1.59 83.47,37.17 79.31,33.02 IC4.16
ND0
  Top 0.203: IC7.18 46.29,32.7 59.36,45.77 IC1.33
ND1
  Top 0.203: IC7.17 47.56,32.38 60.45,45.27 IC1.34
ND2
  Top 0.203: IC1.35 70.43,44.77 70.42,44.77 60.58,44.77 48.83,33.02 IC7.16
ND3
  Top 0.203: IC1.40 73.97,41.33 73.6,40.96 58.36,40.96 50.1,32.7 IC7.15
ND4
  Top 0.203: IC1.41 74.47,41.19 73.6,40.32 58.36,40.32 51.37,33.34 IC7.14
ND5
  Top 0.203: IC1.42 74.97,41.06 73.6,39.69 58.36,39.69 52.64,33.97 IC7.13
ND6
  Top 0.203: IC1.43 75.47,40.92 73.6,39.05 58.36,39.05 53.91,34.61 IC7.12
ND7
  Top 0.203: IC1.45 76.47,41.29 73.6,38.42 58.36,38.42 55.18,35.24 IC7.11
NDIR  (via drill 0.61)
  Top 0.203: v40.89,29.53 40.89,30.8 42.8,32.7 42.8,34.61 44.07,35.88 48.2,35.88 59.09,46.77 IC1.31
  Top 0.254: IC7.1 43.75,21.59
  Top 0.305: IC7.1 v43.75,24.77
  Bottom 0.203: v43.75,24.77 43.75,26.67 v40.89,29.53
NEN
  Top 0.203: IC7.19 45.02,32.07 59.23,46.27 IC1.32
NIORQ
  Top 0.203: IC1.60 83.97,36.41 80.58,33.02 IC4.15
NRD
  Top 0.203: IC1.57 82.47,38.4 76.77,32.7 IC4.18
NRESET
  Top 0.203: IC1.62 84.97,36.13 81.85,33.02 IC4.14
NWR
  Top 0.203: IC1.58 82.97,37.95 78.04,33.02 IC4.17
PS2_CLK1
  Top 0.203: R5.1 125.68,75.89 125.98,76.2 127.89,76.2 | 124.71,75.88 108.52,75.88 106.62,73.98 106.62,58.42 97.97,49.77 IC1.84
  Top 0.254: 124.71,75.88 R5.1
  Top 0.406: 127.89,76.2 D3.3
PS2_CLK2
  Top 0.203: D2.3 127.89,91.12 126.62,91.12 126,90.5 R3.1 124.71,90.49 123.44,90.49 121.86,88.9 121.86,82.87 120.9,81.92 107.25,81.92 105.35,80.01 105.35,58.42 98.2,51.27 IC1.87
PS2_DAT1
  Top 0.203: R4.1 125.68,73.65 126.3,73.03 127.89,73.03 | R4.1 109.16,73.66 107.25,71.75 107.25,58.42 98.1,49.27 IC1.83
  Top 0.254: R4.1
  Top 0.406: 127.89,73.03 D4.3
PS2_DAT2
  Top 0.203: D1.3 127.89,87.63 126.62,87.63 126,88.25 R1.1 124.71,88.27 123.76,88.27 122.49,87 122.49,82.87 120.9,81.28 107.89,81.28 105.98,79.38 105.98,58.42 98.33,50.77 IC1.86
RD  (via drill 0.61)
  Top 0.203: v75.18,6.35 75.18,13.34 75.5,13.65 IC4.2 | U$1.16 44.7,9.53 44.7,6.67 43.75,5.71 8.51,5.71 6.6,7.62 6.6,12.38 7.56,13.34 7.56,66.36 X1.RD
  Bottom 0.203: U$1.16 43.43,8.26 45.97,5.71 61.53,5.71 62.48,6.67 74.87,6.67 v75.18,6.35
RESET  (via drill 0.61)
  Top 0.203: U$1.28 73.91,5.71 72.01,3.81 8.51,3.81 2.48,9.84 2.48,79.69 3.43,80.64 11.37,80.64 12,81.28 12,82.55 11.37,83.19 9.14,83.19 8.51,83.82 8.51,86.04 9.46,87 X1.RESET | IC4.6 80.58,19.37 81.53,18.41 v81.53,13.34
  Bottom 0.203: U$1.28 73.91,12.7 74.55,13.34 v81.53,13.34
ROT
  Top 0.203: R14.1 139.32,63.5 139.31,63.51 R15.1 139.32,65.41 R15.1 R16.1 139.32,67.31 139.32,67.94 139.64,68.26 139.79,68.42 CN6.1
RTS_FPGA
  Top 0.203: IC6.11 109.47,37.15 106.62,40.01 96.14,40.01 94.55,38.42 89.15,38.42 86.97,40.6 IC1.66
RXD
  Top 0.203: 124.4,26.35 144.72,26.35 145.67,25.4 147.26,25.4 X3.2
  Top 0.254: IC6.8 119,39.69 118.05,38.73 118.05,32.38 116.14,30.48 116.14,26.99 116.78,26.35 124.4,26.35
RXD_FPGA
  Top 0.203: IC1.69 88.47,40.38 89.15,39.69 94.55,39.69 96.14,41.27 106.62,41.27 108.2,39.69 IC6.9
SLEEPN  (via drill 0.61)
  Top 0.203: ST3.7 33.91,92.39 45.97,80.33 45.97,65.41 61.53,49.85 v61.53,48.26 | v61.53,43.81 61.53,42.55 62.48,41.59 67.25,41.59 67.55,41.9 R2.1 69.15,42.86 69.74,42.27 IC1.37
  Bottom 0.203: v61.53,43.81 v61.53,48.26
SRAM_A0
  Top 0.203: IC2.1 79.63,69.22 | IC1.131 78.97,67.6 79.63,68.26 IC2.1 | IC2.1 79.63,74.93 78.68,75.88 78.68,81.6 79.63,82.55 IC3.1 79.63,84.77
SRAM_A1
  Top 0.203: IC1.129 79.97,67.01 80.9,67.94 IC2.2 80.9,74.93 | 80.9,74.93 80.91,73.33 | 80.9,74.93 80.26,75.56 80.26,81.6 80.9,82.23 IC3.2
SRAM_A2
  Top 0.203: IC1.126 81.47,66.92 82.17,67.63 82.17,69.85 82.18,69.85 | 82.18,69.85 IC2.3 | 82.18,69.85 82.18,74.92 81.53,75.56 81.53,81.6 82.17,82.23 IC3.3 82.17,84.77
SRAM_A3
  Top 0.203: IC1.124 82.47,66.66 83.44,67.63 IC2.4 83.44,74.93 82.8,75.56 82.8,81.6 83.44,82.23 IC3.4 83.44,84.77
SRAM_A4
  Top 0.203: 94.87,84.77 IC3.13 94.87,82.23 94.23,81.6 94.23,75.56 94.87,74.93 IC2.13 94.87,68.26 98.68,64.45 98.68,60.64 95.81,57.77 IC1.100
SRAM_A5
  Top 0.203: 96.15,84.95 IC3.14 96.14,82.23 95.5,81.6 95.5,75.56 96.14,74.93 IC2.14 96.14,68.26 99.95,64.45 99.95,60.33 95.9,56.27 IC1.97
SRAM_A6
  Top 0.203: 97.41,84.77 IC3.15 97.41,82.23 96.77,81.6 96.77,75.56 97.41,74.93 IC2.15 97.41,68.26 101.22,64.45 101.22,60.33 96.17,55.27 IC1.95
SRAM_A7
  Top 0.203: 98.68,84.77 IC3.16 98.68,82.23 98.04,81.6 98.04,75.56 98.68,74.93 IC2.16 98.68,68.26 102.49,64.45 102.49,60.33 96.44,54.27 IC1.93
SRAM_A8
  Top 0.203: IC3.17 98.69,94.79 | IC2.17 98.68,79.69 | IC2.17 98.68,75.56 99.31,74.93 99.31,68.26 103.12,64.45 103.12,60.33 96.57,53.77 IC1.92 | IC2.17 98.68,81.6 99.63,82.55 99.63,89.22 98.68,90.17 IC3.17 | IC3.17 98.68,94.61
SRAM_A9
  Top 0.203: IC3.18 97.42,94.79 | IC3.18 97.41,94.61 | IC3.18 97.41,90.17 98.04,89.53 98.04,82.23 97.41,81.6 IC2.18 97.41,75.56 98.04,74.93 98.04,68.26 101.85,64.45 101.85,60.33 96.3,54.77 IC1.94
SRAM_A10
  Top 0.203: 96.15,94.79 IC3.19 96.14,90.17 96.77,89.53 96.77,82.23 96.14,81.6 IC2.19 96.14,75.56 96.77,74.93 96.77,68.26 100.58,64.45 100.58,60.33 96.03,55.77 IC1.96
SRAM_A11
  Top 0.203: 94.88,94.79 IC3.20 94.87,90.17 95.5,89.53 95.5,82.23 94.87,81.6 IC2.20 94.87,75.56 95.5,74.93 95.5,68.26 99.31,64.45 99.31,60.64 95.94,57.27 IC1.99
SRAM_A12
  Top 0.203: 93.61,94.79 IC3.21 93.6,90.17 94.23,89.53 94.23,82.23 93.6,81.6 IC2.21 93.6,75.56 94.23,74.93 94.23,68.26 98.04,64.45 98.04,60.96 95.86,58.77 IC1.102
SRAM_A13
  Top 0.203: IC3.29 83.45,94.79 | IC1.123 82.97,66.52 84.07,67.63 84.07,74.93 83.44,75.56 IC2.29 | IC2.29 83.44,79.69 | IC2.29 83.44,81.6 84.07,82.23 84.07,86.04 83.44,86.68 IC3.29 | IC3.29 83.44,94.61
SRAM_A14
  Top 0.203: IC1.125 81.97,66.79 82.8,67.63 82.8,74.93 82.17,75.56 IC2.30 | IC2.30 82.17,79.69 | IC2.30 82.17,81.6 82.8,82.23 82.8,89.53 82.17,90.17 IC3.30 82.17,94.61
SRAM_A15
  Top 0.203: IC1.128 80.47,66.88 81.53,67.94 81.53,74.93 80.9,75.56 IC2.31 80.9,81.6 81.53,82.23 81.53,89.53 80.9,90.17 IC3.31
SRAM_A16
  Top 0.203: IC1.130 79.47,67.15 80.26,67.94 80.26,74.93 79.63,75.56 IC2.32 79.63,81.6 80.26,82.23 80.26,89.53 79.63,90.17 IC3.32
SRAM_CE
  Top 0.203: IC1.122 83.47,66.39 84.71,67.63 IC2.5
SRAM_CE1  (via drill 0.61)
  Top 0.203: v84.71,87.63 IC3.5 | IC1.132 78.47,75.46 78.04,75.88 v78.04,87.63
  Bottom 0.203: v78.04,87.63 v84.71,87.63
SRAM_D0
  Top 0.203: IC1.118 85.47,66.8 85.98,67.31 IC2.6 85.98,71.12 85.66,71.44 85.66,74.93 84.71,75.88 84.71,77.79 85.34,78.42 85.34,81.6 85.98,82.23 IC3.6 85.98,84.77
SRAM_D1
  Top 0.203: IC1.116 86.47,66.53 87.25,67.31 IC2.7 87.25,71.12 86.93,71.44 86.93,74.93 85.98,75.88 85.98,77.79 86.61,78.42 86.61,81.6 87.25,82.23 IC3.7
SRAM_D2
  Top 0.203: IC1.114 87.47,66.26 89.15,67.94 90.42,67.94 91.06,68.58 IC2.10 91.06,74.93 90.42,75.56 90.42,81.6 91.06,82.23 IC3.10
SRAM_D3
  Top 0.203: IC1.105 95.45,60.27 96.14,60.96 96.14,64.45 92.33,68.26 IC2.11 92.33,74.93 91.69,75.56 91.69,81.6 92.33,82.23 IC3.11 92.33,84.77
SRAM_D4
  Top 0.203: 92.34,94.79 IC3.22 92.33,90.17 92.96,89.53 92.96,82.23 92.33,81.6 92.33,79.38 | 92.33,79.69 IC2.22 92.33,79.38 | 92.33,79.38 92.33,75.56 92.96,74.93 92.96,68.26 96.77,64.45 96.77,60.96 95.59,59.77 IC1.104
SRAM_D5
  Top 0.203: 91.07,94.79 IC3.23 91.06,90.17 91.69,89.53 91.69,82.23 91.06,81.6 91.06,79.38 | IC1.113 87.97,66.12 89.15,67.31 91.06,67.31 91.69,67.94 91.69,74.93 91.06,75.56 91.06,79.38 | 91.06,79.69 IC2.23 91.06,79.38
SRAM_D6
  Top 0.203: IC3.26 87.26,94.79 | IC1.115 86.97,66.39 87.88,67.31 87.88,71.12 87.57,71.44 87.57,74.93 86.61,75.88 86.61,77.79 87.25,78.42 IC2.26 87.25,81.6 87.88,82.23 87.88,86.04 87.25,86.68 IC3.26 | IC3.26 87.25,94.61
SRAM_D7
  Top 0.203: IC1.117 85.97,66.66 86.61,67.31 86.61,71.12 86.3,71.44 86.3,74.93 85.34,75.88 85.34,77.79 85.98,78.42 IC2.27 85.98,81.6 86.61,82.23 86.61,89.53 85.98,90.17 IC3.27
SRAM_OE
  Top 0.203: IC1.120 84.47,66.75 85.34,67.63 85.34,71.12 85.03,71.44 85.03,74.93 84.07,75.88 84.07,77.79 84.71,78.42 IC2.28 84.71,81.6 85.34,82.23 85.34,86.04 85.98,86.68 85.98,88.9 84.71,90.17 IC3.28 84.71,94.61
SRAM_RW
  Top 0.203: 93.61,84.95 IC3.12 93.6,82.23 92.96,81.6 92.96,75.56 93.6,74.93 IC2.12 93.6,68.26 97.41,64.45 97.41,60.96 95.72,59.27 IC1.103
TXD
  Top 0.254: IC6.7 122.49,38.42 122.81,38.73 126.3,38.73 126.94,38.1 126.94,29.21 129.16,26.99 144.72,26.99 145.99,28.26 X3.3
TXD_FPGA
  Top 0.203: IC6.10 108.84,38.42 106.62,40.64 96.14,40.64 94.55,39.05 89.15,39.05 87.47,40.74 IC1.67
V+_IC1
  Top 0.254: 121.22,32.07 IC6.2 119,32.07 117.09,30.16 C55.1
V-_IC1
  Top 0.254: IC6.6 122.81,37.15 123.44,37.78 125.03,37.78 C52.2 125.03,37.86
VCC  (via drill 0.61, 0.81 pad 1.42)  (2 unrouted)
  Top 0.203: IC1.36 66.12,44.27 65.66,43.81 65.66,42.86 R2.2 | C4.2 59.36,33.02 59.31,33.02 59.31,32.7 | 74.23,20.64 IC4.1 | v42.16,30.8 42.21,30.75 | 73.47,62.87 73.47,62.36 v73.6,62.23 | 73.47,62.87 IC1.142 | 73.47,62.87 72.96,62.87 72.97,62.87 IC1.143 72.97,63.82 72.96,63.82 72.96,65.41 71.69,66.67 70.1,66.67 | 70.1,67.64 70.1,67.63 | 70.1,67.64 70.1,71.75 69.47,72.39 66.61,72.39 65.98,73.03 R127.2 63.45,75.89 63.44,75.88 R24.2 | IC8.4 42.12,54.98 | v104.39,30.8 104.39,29.84 106.13,28.11 D5.2 | R58.2 68.2,67.63 69.15,66.67 70.1,66.67 | 70.1,66.67 70.1,67.64 | IC9.2@1 24.38,38.42 25.02,38.42
  Top 0.254: IC5.1 58.99,21.59 | IC1.36 72.19,44.27 v72.33,44.13 73.28,44.13 73.47,43.95 IC1.39 | IC1.19 71.44,52.77 v72.01,53.34 v72.01,54.61 71.37,55.24 71.35,55.24 71.35,55.27 IC1.14 | IC1.8 71.54,58.27 v72.01,58.74 | IC1.133 77.97,62.47 v77.72,62.23 | IC1.119 84.97,62.92 85.66,62.23 v86.61,62.23 v87.88,62.23 88.47,62.81 IC1.112 | IC1.108 90.92,61.77 90.11,60.96 v90.11,60.33 90.55,60.77 IC1.106 | IC1.98 91,56.77 v90.42,56.2 v90.42,53.98 91.13,53.27 IC1.91 | IC1.73 90.92,44.27 v90.11,45.09 | 84.39,43.5 v84.07,43.81 | 84.39,43.5 84.47,43.41 | IC1.61 84.47,43.42 84.39,43.5 | C55.2 115.2,28.88 v113.28,30.8 | IC1.88 90.44,51.77 v90.11,51.44 | IC1.49 78.47,42.97 79.31,43.81 v79.63,43.81 | IC1.68 87.97,43.1 v87.25,43.81
  Top 0.305: IC5.1 v58.99,22.86 | v74.23,28.57 IC4.20 | v58.99,28.57 IC5.20 58.99,32.38 59.31,32.7 | 88.52,71.44 v88.52,71.75 | IC4.1 v74.23,22.86 | C1.2 73.28,19.68 74.23,20.64 | C31.2 43.75,33.66 IC7.20
  Top 0.406: 126.94,93.66 D2.2 126.94,93.34 126.94,93.35 v126.94,95.25 | v126.94,80.33 | D4.2 128.84,70.48 v128.84,68.9 128.84,67.63 v123.76,62.55 | IC2.8 88.52,71.44 | IC3.8 88.52,86.68 v88.2,87 | v89.79,91.44 IC3.24 | IC2.24 89.79,77.47 v89.47,77.15 | v126.94,80.33 126.94,81.6 v128.84,83.5 128.84,85.09 D1.2 | D3.2 126.94,78.74 v126.94,80.33 | SV1.6 114.24,54.61 110.11,54.61 108.2,52.7 v105.98,52.7 | 42.21,30.75 IC7.20 | IC8.4 IC8.1 42.16,47.31 v41.53,46.67 | 42.12,54.98 C2.2
  Top 0.61: v107.89,30.8 IC6.16 112.65,30.8 | 112.65,30.8 v113.28,30.8 | 112.65,30.8 112.75,30.7 | v83.76,26.35 v95.19,26.35
  Top 1.016: IC9.2 v24.38,32.38 v24.38,37.78 25.02,38.42 | v19.62,91.44 v18.99,90.81 15.81,87.63 15.81,63.18 16.76,62.23 | 16.76,62.23 v18.03,62.23 | 16.76,62.23 15.81,61.28 v15.81,55.56 v15.81,54.61
  Bottom 0.203: 15.18,47.62 15.49,47.94 | 114.9,32.42 114.9,31.46 114.87,31.43
  Bottom 0.305: 88.8,73.34 88.84,73.34 | v58.99,28.57 58.99,29.84 | 15.49,47.94 15.49,48.26
  Bottom 0.406: 36.45,29.53 36.13,29.21 | 37.4,29.21 37.08,29.53 | v128.84,83.5 128.84,93.34 v126.94,95.25 | v128.84,68.9 128.84,78.42 v126.94,80.33 | 114.9,32.42 115.51,33.02 115.51,33.66 115.64,33.66 C5.2 | 123.76,62.23 v123.76,62.55 118.76,57.55 C3.2 118.68,55.9 118.68,55.88 SV1.6
  Bottom 0.61: 77.41,26.35 76.77,26.35 | 77.41,26.35 v83.76,26.35 | v95.19,26.35 99.95,26.35 v104.39,30.8 v107.89,30.8 | 114.9,31.43 114.87,31.43 114.24,30.8 v113.28,30.8 | 91.69,52.7 v105.98,52.7 | C57.1 24.27,32.5 v24.38,32.38 24.37,32.37 24.37,31.13 24.38,31.11 24.37,31.11 C59.2 | 77.41,26.35 77.09,26.67 | 77.09,26.04 77.41,26.35
  Bottom 1.016: 72.33,28.57 71.69,29.21 71.69,43.18 | C66.2 88.8,73.34 | v18.99,90.81 v19.62,91.44 23.75,95.57 ST3.2 | ST3.2 26.61,95.57 | ST3.2 ST3.4 | 88.84,90.49 v89.79,91.44 | 15.81,48.26 15.81,46.99 | 15.81,48.26 v15.81,54.61 v15.81,55.56 | 90.74,62.87 89.79,63.82 | 68.83,34.29 70.1,35.56 | 43.43,34.29 42.16,35.56 | 34.86,36.2 34.23,36.83 | 16.76,47.31 15.81,48.26
  other vias: 19.94,42.23 22.16,42.23 24.38,42.23 26.61,42.23 28.83,42.23 19.94,40.01 22.16,40.01 24.38,40.01 26.61,40.01 28.83,40.01 19.94,37.78 22.16,37.78 26.61,37.78 28.83,37.78
  pour Bottom (isolate 0.406): 34.54,34.61 77.09,34.61 77.09,20.32 34.54,20.32
  pour Bottom (isolate 0.406): 69.79,43.5 69.79,28.89 77.09,28.89 77.09,43.5
  pour Bottom (isolate 0.406): 69.79,63.18 92.33,63.18 92.33,43.18 69.79,43.18
  pour Bottom (isolate 0.406): 89.15,91.12 86.93,91.12 86.93,81.6 89.15,79.38 89.15,76.2 86.93,73.98 86.93,63.18 90.11,63.18 90.11,68.9 89.15,69.85 89.15,74.61 90.42,75.88 90.42,82.23 89.15,83.5
  pour Bottom (isolate 0.406): 15.18,36.83 15.18,47.62 42.48,47.62 42.48,29.53 34.54,29.53 34.54,36.83
VCC/2  (via drill 0.61)  (1 unrouted)
  Top 0.203: C6.2 133.6,88.27 133.62,88.25 | R8.2 131.06,88.27 131.08,88.25 | 135.19,88.25 135.19,88.27
  Top 0.254: 131.06,88.27 R9.2 | 131.06,75.56 R7.2 C7.2 | 133.62,88.25 135.19,88.25 | 131.08,88.25 133.59,88.25 | 135.19,88.27 137.73,90.81 v141.54,90.81 | v141.86,84.45 137.73,84.45 v137.1,83.82 | v134.56,80.33 133.29,79.06 133.29,76.2 132.65,75.56 131.06,75.56 | 131.06,75.56 R6.2
  Top 0.406: R8.2 131.06,87.95 | 133.59,88.25 133.6,88.27
  Top 1.016: U$1.4 U$1.5 | IC9.3 26.92,28.89 v28.51,28.89 v29.46,28.89
  Top 1.27: IC9.3 26.92,26.99 25.34,25.4 17.08,25.4 15.49,23.81 U$1.5
  Bottom 0.254: v137.1,83.82 137.1,82.87 v134.56,80.33
  Bottom 1.016: PAD3.1 12.32,9.21 12.95,9.84 U$1.4 U$1.5 | v28.51,28.89 v29.46,28.89 29.46,30.8 30.73,30.8 31.69,31.75 31.69,34.18 C63.1
  Bottom 1.27: 159.32,78.74 159.32,4.45 156.15,1.27 21.21,1.27 15.49,6.99 U$1.5 | 159.32,78.74 159.32,85.41 | 139,99.06 34.86,99.06 33.91,98.11 ST3.8 ST3.6 | 139,99.06 141.22,99.06 | 159.32,78.74 157.73,80.33 | 139,99.06 140.91,97.16
  pour Bottom (isolate 0.406): 159.96,80.01 140.27,80.01 140.27,99.69 159.96,99.69
VGA_BL0
  Top 0.203: 135.51,54.29 134.87,53.66 134.87,50.8 129.16,45.09 98.04,45.09 97.36,45.77 IC1.76 | 135.51,54.29 135.74,54.53 | R19.2 135.83,54.61 135.51,54.29
VGA_BL1
  Top 0.203: 136.14,52.39 135.51,51.75 135.51,50.8 129.16,44.45 97.73,44.45 97.4,44.77 IC1.74 | 136.14,52.39 136.38,52.62 | R18.2 136.46,52.7 136.14,52.39
VGA_BL2
  Top 0.203: 135.83,50.48 129.16,43.81 96.77,43.81 94.55,41.59 90.42,41.59 89.97,42.05 IC1.72 | 135.83,50.48 136.06,50.72 | R17.2 136.14,50.8 135.83,50.48
VGA_GR0
  Top 0.203: 132.97,60.33 132.97,50.8 129.16,46.99 99,46.99 98.71,47.27 IC1.79
  Top 0.254: R13.2 133.6,60.96 132.97,60.33
VGA_GR1
  Top 0.203: 134.24,58.74 133.6,58.1 133.6,50.8 129.16,46.35 98.68,46.35 98.26,46.77 IC1.78 | 134.24,58.74 134.47,58.97 | R12.2 134.56,59.05 134.24,58.74
VGA_GR2
  Top 0.203: 134.87,56.83 134.24,56.2 134.24,50.8 129.16,45.72 98.36,45.72 97.81,46.27 IC1.77 | 134.87,56.83 135.11,57.07 | R11.2 135.19,57.15 134.87,56.83
VGA_HSYNC
  Top 0.203: R22.2 134.24,48.26 128.84,42.86 107.25,42.86 106.93,42.55 96.14,42.55 94.55,40.96 89.79,40.96 89.47,41.28 IC1.71
VGA_RD0
  Top 0.203: R16.2 135.51,67.31 134.56,66.36 134.56,63.82 131.06,60.33 131.06,50.8 129.16,48.9 99.63,48.9 99.51,48.77 IC1.82
VGA_RD1
  Top 0.203: 135.83,65.09 135.19,64.45 135.19,63.82 131.7,60.33 131.7,50.8 129.16,48.26 99.63,48.26 99.62,48.27 IC1.81 | 135.83,65.09 136.06,65.32 | R15.2 136.14,65.41 135.83,65.09
VGA_RD2
  Top 0.203: 135.19,63.18 132.33,60.33 132.33,50.8 129.16,47.62 99.31,47.62 99.17,47.77 IC1.80 | 135.19,63.18 135.43,63.42 | R14.2 135.51,63.5 135.19,63.18
VGA_VSYNC
  Top 0.203: R23.2 132.97,46.35 128.84,42.23 107.25,42.23 106.93,41.91 96.14,41.91 94.55,40.32 89.47,40.32 88.97,40.83 IC1.70
WR  (via drill 0.61)
  Top 0.203: v77.72,6.99 v77.72,16.83 77.72,17.78 76.77,18.73 IC4.3
  Bottom 0.203: U$1.17 45.97,7.94 47.56,6.35 61.21,6.35 62.17,7.3 77.09,7.3 77.41,6.99 v77.72,6.99 | X1.WR 8.51,62.23 8.51,46.04 9.46,45.09 11.05,45.09 12,44.13 12,32.07 12.32,31.75 12.32,30.48 13.59,29.21 13.59,27.3 14.22,26.67 17.08,26.67 19.62,24.13 32,24.13 35.81,20.32 40.26,20.32 41.21,19.37 55.5,19.37 57.4,17.46 68.52,17.46 69.15,16.83 v77.72,16.83

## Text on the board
Top: A.V. | 2007
tNames: Optional | Connector
tValues: EXTENSION | AUDIO | GDP64HS-FPGA | JTAG | INT EN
